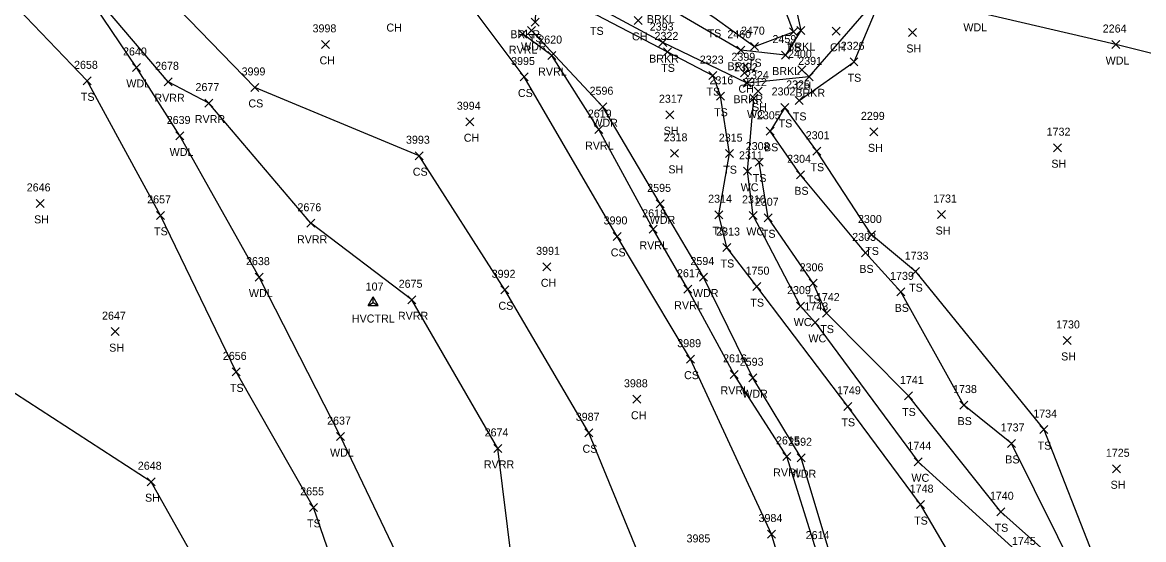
# Model space of a CAD drawing. Extents: x 1482574 to 1485769, y 580696 to 595649.
# Drawn here: x 1484779.3 to 1485059.6, y 582325.6 to 582454.9 of the extents above; entities that cross this region are included whole.
import ezdxf

# ---------------------------------------------------------------- set-up
doc = ezdxf.new("R2010")
doc.units = 0
for name, color, linetype in [('C_A', 7, 'Continuous'), ('C_I', 7, 'Continuous'), ('CPSM', 7, 'Continuous'), ('L_A', 7, 'Continuous'), ('L_I', 7, 'Continuous'), ('L_TIC', 7, 'Continuous'), ('LAWA', 7, 'Continuous'), ('LAWE', 7, 'Continuous'), ('LELB', 7, 'Continuous'), ('LSOGP', 7, 'Continuous')]:
    doc.layers.add(name, color=color, linetype=linetype)

msp = doc.modelspace()

# ---------------------------------------------------------------- linework, layer by layer
at = {"layer": 'CPSM'}
for p, q in [((1484865.7, 582384.13), (1484866.95, 582386.3)), ((1484865.7, 582384.13), (1484866.95, 582384.85)), ((1484865.7, 582384.13), (1484868.2, 582384.13)), ((1484868.2, 582384.13), (1484866.95, 582386.3)), ((1484866.95, 582384.85), (1484866.95, 582386.3)), ((1484866.95, 582384.85), (1484866.95, 582384.85)), ((1484866.95, 582384.85), (1484868.2, 582384.13))]:
    msp.add_line(p, q, dxfattribs=at)
at = {"layer": 'L_TIC'}
for points in [[(1484905.56, 582451.88), (1484907.56, 582453.88)], [(1484907.56, 582451.88), (1484905.56, 582453.88)], [(1484906.45, 582453.96), (1484908.45, 582455.96)], [(1484908.45, 582453.96), (1484906.45, 582455.96)], [(1484932.17, 582454.41), (1484934.17, 582456.41)], [(1484934.17, 582454.41), (1484932.17, 582456.41)], [(1484972.84, 582451.87), (1484974.84, 582453.87)], [(1484974.84, 582451.87), (1484972.84, 582453.87)], [(1484903.31, 582451.08), (1484905.31, 582453.08)], [(1484905.31, 582451.08), (1484903.31, 582453.08)], [(1484971.06, 582451.57), (1484973.06, 582453.57)], [(1484973.06, 582451.57), (1484971.06, 582453.57)], [(1484981.67, 582451.67), (1484983.67, 582453.67)], [(1484983.67, 582451.67), (1484981.67, 582453.67)], [(1485000.76, 582451.38), (1485002.76, 582453.38)], [(1485002.76, 582451.38), (1485000.76, 582453.38)], [(1484854.07, 582448.41), (1484856.07, 582450.41)], [(1484856.07, 582448.41), (1484854.07, 582450.41)], [(1484938.36, 582448.84), (1484940.36, 582450.84)], [(1484940.36, 582448.84), (1484938.36, 582450.84)], [(1484939.56, 582446.53), (1484941.56, 582448.53)], [(1484941.56, 582446.53), (1484939.56, 582448.53)], [(1484957.9, 582446.95), (1484959.9, 582448.95)], [(1484959.9, 582446.95), (1484957.9, 582448.95)], [(1484961.25, 582447.84), (1484963.25, 582449.84)], [(1484963.25, 582447.84), (1484961.25, 582449.84)], [(1485051.65, 582448.37), (1485053.65, 582450.37)], [(1485053.65, 582448.37), (1485051.65, 582450.37)], [(1485051.65, 582448.37), (1485053.65, 582450.37)], [(1485053.65, 582448.37), (1485051.65, 582450.37)], [(1484910.63, 582445.6), (1484912.63, 582447.6)], [(1484912.63, 582445.6), (1484910.63, 582447.6)], [(1484969.06, 582445.73), (1484971.06, 582447.73)], [(1484971.06, 582445.73), (1484969.06, 582447.73)], [(1484986.17, 582444.06), (1484988.16, 582446.06)], [(1484988.16, 582444.06), (1484986.17, 582446.06)], [(1484806.83, 582442.63), (1484808.83, 582444.63)], [(1484808.83, 582442.63), (1484806.83, 582444.63)], [(1484950.88, 582440.6), (1484952.88, 582442.6)], [(1484952.88, 582440.6), (1484950.88, 582442.6)], [(1484958.79, 582441.31), (1484960.79, 582443.31)], [(1484960.79, 582441.31), (1484958.79, 582443.31)], [(1484973.09, 582442.04), (1484975.09, 582444.03)], [(1484975.09, 582442.04), (1484973.09, 582444.03)], [(1484794.49, 582439.29), (1484796.49, 582441.29)], [(1484796.49, 582439.29), (1484794.49, 582441.29)], [(1484814.75, 582439.05), (1484816.75, 582441.05)], [(1484816.75, 582439.05), (1484814.75, 582441.05)], [(1484903.71, 582440.25), (1484905.71, 582442.25)], [(1484905.71, 582440.25), (1484903.71, 582442.25)], [(1484959.42, 582438.71), (1484961.42, 582440.7)], [(1484961.42, 582438.71), (1484959.42, 582440.7)], [(1484974.92, 582440.29), (1484976.92, 582442.29)], [(1484976.92, 582440.29), (1484974.92, 582442.29)], [(1484836.34, 582437.64), (1484838.34, 582439.64)], [(1484838.34, 582437.64), (1484836.34, 582439.64)], [(1484952.78, 582435.43), (1484954.78, 582437.43)], [(1484954.78, 582435.43), (1484952.78, 582437.43)], [(1484961.13, 582434.96), (1484963.12, 582436.96)], [(1484963.12, 582434.96), (1484961.13, 582436.96)], [(1484962.18, 582436.72), (1484964.18, 582438.72)], [(1484964.18, 582436.72), (1484962.18, 582438.72)], [(1484824.86, 582433.73), (1484826.86, 582435.73)], [(1484826.86, 582433.73), (1484824.86, 582435.73)], [(1484923.38, 582432.82), (1484925.38, 582434.81)], [(1484925.38, 582432.82), (1484923.38, 582434.81)], [(1484968.91, 582432.64), (1484970.91, 582434.63)], [(1484970.91, 582432.64), (1484968.91, 582434.63)], [(1484972.46, 582434.39), (1484974.46, 582436.39)], [(1484974.46, 582434.39), (1484972.46, 582436.39)], [(1484940.09, 582430.81), (1484942.09, 582432.81)], [(1484942.09, 582430.81), (1484940.09, 582432.81)], [(1484890.13, 582429.07), (1484892.13, 582431.06)], [(1484892.13, 582429.07), (1484890.13, 582431.06)], [(1484922.38, 582427.1), (1484924.37, 582429.1)], [(1484924.37, 582427.1), (1484922.38, 582429.1)], [(1484965.22, 582426.67), (1484967.22, 582428.67)], [(1484967.22, 582426.67), (1484965.22, 582428.67)], [(1484991.16, 582426.53), (1484993.16, 582428.53)], [(1484993.16, 582426.53), (1484991.16, 582428.53)], [(1484817.67, 582425.5), (1484819.67, 582427.5)], [(1484819.67, 582425.5), (1484817.67, 582427.5)], [(1484941.27, 582421.16), (1484943.27, 582423.16)], [(1484943.27, 582421.16), (1484941.27, 582423.16)], [(1484955.07, 582421.08), (1484957.07, 582423.08)], [(1484957.07, 582421.08), (1484955.07, 582423.08)], [(1484976.87, 582421.69), (1484978.87, 582423.69)], [(1484978.87, 582421.69), (1484976.87, 582423.69)], [(1485037.01, 582422.57), (1485039.01, 582424.57)], [(1485039.01, 582422.57), (1485037.01, 582424.57)], [(1484877.43, 582420.56), (1484879.43, 582422.56)], [(1484879.43, 582420.56), (1484877.43, 582422.56)], [(1484962.44, 582418.97), (1484964.44, 582420.97)], [(1484964.44, 582418.97), (1484962.44, 582420.97)], [(1484959.53, 582416.67), (1484961.53, 582418.67)], [(1484961.53, 582416.67), (1484959.53, 582418.67)], [(1484972.8, 582415.79), (1484974.79, 582417.79)], [(1484974.79, 582415.79), (1484972.8, 582417.79)], [(1484782.72, 582408.64), (1484784.72, 582410.64)], [(1484784.72, 582408.64), (1484782.72, 582410.64)], [(1484937.73, 582408.53), (1484939.73, 582410.53)], [(1484939.73, 582408.53), (1484937.73, 582410.53)], [(1484812.78, 582405.65), (1484814.78, 582407.65)], [(1484814.78, 582405.65), (1484812.78, 582407.65)], [(1484952.4, 582405.81), (1484954.4, 582407.81)], [(1484954.4, 582405.81), (1484952.4, 582407.81)], [(1484960.95, 582405.63), (1484962.95, 582407.63)], [(1484962.95, 582405.63), (1484960.95, 582407.63)], [(1484964.72, 582405.04), (1484966.72, 582407.04)], [(1484966.72, 582405.04), (1484964.72, 582407.04)], [(1485008.07, 582405.86), (1485010.07, 582407.86)], [(1485010.07, 582405.86), (1485008.07, 582407.86)], [(1484850.4, 582403.67), (1484852.4, 582405.67)], [(1484852.4, 582403.67), (1484850.4, 582405.67)], [(1484935.96, 582402.16), (1484937.96, 582404.16)], [(1484937.96, 582402.16), (1484935.96, 582404.16)], [(1484926.92, 582400.38), (1484928.92, 582402.38)], [(1484928.92, 582400.38), (1484926.92, 582402.38)], [(1484990.57, 582400.75), (1484992.57, 582402.75)], [(1484992.57, 582400.75), (1484990.57, 582402.75)], [(1484954.4, 582397.62), (1484956.4, 582399.61)], [(1484956.4, 582397.62), (1484954.4, 582399.61)], [(1484989.06, 582396.26), (1484991.06, 582398.26)], [(1484991.06, 582396.26), (1484989.06, 582398.26)], [(1484837.48, 582390.2), (1484839.48, 582392.2)], [(1484839.48, 582390.2), (1484837.48, 582392.2)], [(1484909.39, 582392.78), (1484911.39, 582394.78)], [(1484911.39, 582392.78), (1484909.39, 582394.78)], [(1484948.53, 582390.22), (1484950.53, 582392.22)], [(1484950.53, 582390.22), (1484948.53, 582392.22)], [(1485001.53, 582391.58), (1485003.53, 582393.57)], [(1485003.53, 582391.58), (1485001.53, 582393.57)], [(1484961.85, 582387.82), (1484963.85, 582389.82)], [(1484963.85, 582387.82), (1484961.85, 582389.82)], [(1484975.96, 582388.66), (1484977.96, 582390.66)], [(1484977.96, 582388.66), (1484975.96, 582390.66)], [(1484875.65, 582384.54), (1484877.65, 582386.54)], [(1484877.65, 582384.54), (1484875.65, 582386.54)], [(1484898.85, 582387.04), (1484900.85, 582389.04)], [(1484900.85, 582387.04), (1484898.85, 582389.04)], [(1484944.65, 582387.18), (1484946.65, 582389.18)], [(1484946.65, 582387.18), (1484944.65, 582389.18)], [(1484997.89, 582386.52), (1484999.89, 582388.52)], [(1484999.89, 582386.52), (1484997.89, 582388.52)], [(1484972.78, 582382.96), (1484974.78, 582384.96)], [(1484974.78, 582382.96), (1484972.78, 582384.96)], [(1484976.46, 582378.89), (1484978.46, 582380.88)], [(1484978.46, 582378.89), (1484976.46, 582380.88)], [(1484979.33, 582381.21), (1484981.33, 582383.21)], [(1484981.33, 582381.21), (1484979.33, 582383.21)], [(1484801.48, 582376.57), (1484803.48, 582378.57)], [(1484803.48, 582376.57), (1484801.48, 582378.57)], [(1485039.46, 582374.37), (1485041.46, 582376.37)], [(1485041.46, 582374.37), (1485039.46, 582376.37)], [(1484945.25, 582369.7), (1484947.25, 582371.69)], [(1484947.25, 582369.7), (1484945.25, 582371.69)], [(1484831.75, 582366.51), (1484833.75, 582368.51)], [(1484833.75, 582366.51), (1484831.75, 582368.51)], [(1484956.22, 582365.89), (1484958.22, 582367.89)], [(1484958.22, 582365.89), (1484956.22, 582367.89)], [(1484960.86, 582365.04), (1484962.86, 582367.04)], [(1484962.86, 582365.04), (1484960.86, 582367.04)], [(1484931.91, 582359.66), (1484933.91, 582361.66)], [(1484933.91, 582359.66), (1484931.91, 582361.66)], [(1484999.78, 582360.48), (1485001.78, 582362.48)], [(1485001.78, 582360.48), (1484999.78, 582362.48)], [(1484984.61, 582357.89), (1484986.61, 582359.89)], [(1484986.61, 582357.89), (1484984.61, 582359.89)], [(1485013.62, 582358.21), (1485015.62, 582360.21)], [(1485015.62, 582358.21), (1485013.62, 582360.21)], [(1484919.86, 582351.28), (1484921.86, 582353.28)], [(1484921.86, 582351.28), (1484919.86, 582353.28)], [(1485033.66, 582352.07), (1485035.66, 582354.07)], [(1485035.66, 582352.07), (1485033.66, 582354.07)], [(1484857.76, 582350.32), (1484859.76, 582352.32)], [(1484859.76, 582350.32), (1484857.76, 582352.32)], [(1485025.53, 582348.61), (1485027.53, 582350.61)], [(1485027.53, 582348.61), (1485025.53, 582350.61)], [(1484897.14, 582347.38), (1484899.14, 582349.38)], [(1484899.14, 582347.38), (1484897.14, 582349.38)], [(1484969.4, 582345.35), (1484971.4, 582347.35)], [(1484971.4, 582345.35), (1484969.4, 582347.35)], [(1484972.98, 582345.03), (1484974.98, 582347.03)], [(1484974.98, 582345.03), (1484972.98, 582347.03)], [(1485002.21, 582344.02), (1485004.21, 582346.02)], [(1485004.21, 582344.02), (1485002.21, 582346.02)], [(1485051.81, 582342.28), (1485053.81, 582344.28)], [(1485053.81, 582342.28), (1485051.81, 582344.28)], [(1484810.44, 582339.04), (1484812.44, 582341.04)], [(1484812.44, 582339.04), (1484810.44, 582341.04)], [(1484851.03, 582332.63), (1484853.03, 582334.63)], [(1484853.03, 582332.63), (1484851.03, 582334.63)], [(1485002.78, 582333.32), (1485004.78, 582335.32)], [(1485004.78, 582333.32), (1485002.78, 582335.32)], [(1485022.91, 582331.53), (1485024.91, 582333.53)], [(1485024.91, 582331.53), (1485022.91, 582333.53)], [(1484965.56, 582325.96), (1484967.56, 582327.96)], [(1484967.56, 582325.96), (1484965.56, 582327.96)]]:
    msp.add_lwpolyline(points, dxfattribs=at)
at = {"layer": 'LAWA'}
for points in [[(1485052.65, 582449.37), (1485017.08, 582457.66), (1485002.64, 582478.08), (1485021.27, 582509.11), (1485017.76, 582533.46)], [(1484807.83, 582443.63), (1484789.25, 582471.18)], [(1485023.81, 582236.06), (1485015.12, 582258.42), (1485005.47, 582274.43), (1484995.42, 582298.07), (1484981.65, 582320.46), (1484973.98, 582346.03), (1484961.86, 582366.04), (1484949.53, 582391.22), (1484938.73, 582409.53), (1484924.38, 582433.81), (1484906.56, 582452.88)], [(1485075.38, 582443.68), (1485052.65, 582449.37)], [(1484915.16, 582216.76), (1484906.84, 582246.58), (1484892.49, 582281.5), (1484876.39, 582314.59), (1484858.76, 582351.32), (1484838.48, 582391.2), (1484818.67, 582426.5), (1484807.83, 582443.63)]]:
    msp.add_lwpolyline(points, dxfattribs=at)
at = {"layer": 'LAWE'}
for points in [[(1484901.73, 582319.41), (1484898.14, 582348.38), (1484876.65, 582385.54), (1484851.4, 582404.67), (1484825.86, 582434.73), (1484815.75, 582440.05), (1484789.25, 582471.18), (1484766.91, 582495.26), (1484752.64, 582511.53), (1484735.04, 582527.7), (1484703.7, 582557.49), (1484683.77, 582582.65), (1484658.88, 582608.94), (1484640.93, 582626.78), (1484617.5, 582643.87), (1484591.41, 582664.84), (1484560.44, 582694.18), (1484551.66, 582704.27)], [(1484971.03, 582465.85), (1484973.84, 582452.87), (1484970.06, 582446.73), (1484958.9, 582447.95), (1484938.74, 582459.73)], [(1484992.4, 582460.31), (1484975.91, 582441.29), (1484960.42, 582439.7), (1484939.36, 582449.84), (1484914.7, 582463.21)], [(1485020.35, 582235.16), (1485012.7, 582253.51), (1485004.73, 582270.58), (1484994.55, 582289.28), (1484987.31, 582307.44), (1484977.82, 582322.68), (1484970.4, 582346.35), (1484957.22, 582366.89), (1484945.65, 582388.18), (1484936.96, 582403.16), (1484923.38, 582428.1), (1484911.63, 582446.6), (1484904.31, 582452.08)], [(1484973.78, 582383.96), (1484961.95, 582406.63), (1484960.53, 582417.67), (1484962.12, 582435.96)], [(1484977.46, 582379.88), (1484973.78, 582383.96)], [(1484977.46, 582379.88), (1485003.21, 582345.02), (1485029.34, 582321.23), (1485042.39, 582302.12)]]:
    msp.add_lwpolyline(points, dxfattribs=at)
at = {"layer": 'LELB'}
for points in [[(1484934.85, 582318.2), (1484920.86, 582352.28), (1484899.85, 582388.04), (1484878.43, 582421.56), (1484837.34, 582438.64), (1484810.09, 582466.84), (1484787.01, 582495.34), (1484738.45, 582543.61), (1484700.5, 582575.43), (1484669.74, 582613.45), (1484643.11, 582644.14), (1484614.76, 582674.75), (1484580.8, 582689.68), (1484560.67, 582749.78), (1484522.57, 582766.54), (1484495.71, 582790.58), (1484464.85, 582810.97), (1484442.2, 582833.83)], [(1485002.93, 582233.34), (1484992.5, 582263.93), (1484974.17, 582301.29), (1484966.56, 582326.96), (1484946.25, 582370.69), (1484927.92, 582401.38), (1484904.71, 582441.25), (1484886.96, 582465.01), (1484858.7, 582503.29), (1484852.02, 582537.03), (1484804.34, 582588.15), (1484752.2, 582627.41), (1484731.88, 582664.77), (1484681.4, 582685.05), (1484649.84, 582708.59), (1484625.24, 582730.73), (1484593.85, 582761.39), (1484564.6, 582801.05), (1484536.81, 582827.49)], [(1484893.16, 582225.95), (1484874.47, 582260.96), (1484864.03, 582298.79), (1484852.03, 582333.63), (1484832.75, 582367.51), (1484813.78, 582406.65), (1484795.49, 582440.29), (1484770.46, 582466.4), (1484758.58, 582490.95), (1484746.62, 582505.31), (1484737.12, 582520.69), (1484722.27, 582524.68), (1484701.74, 582544.16), (1484684.49, 582562.93), (1484659.56, 582590.31)], [(1484891.21, 582479.17), (1484911.84, 582482.73), (1484927.48, 582474.11), (1484942.04, 582462.79), (1484952.15, 582456.18), (1484962.25, 582448.84), (1484972.06, 582452.57), (1484968.93, 582460.74), (1484958, 582466.03), (1484943.4, 582468.53), (1484932.43, 582474.41), (1484926.65, 582494.11), (1484925.84, 582513.13), (1484942.72, 582524.44)], [(1484907.45, 582454.96), (1484907.96, 582460.72), (1484922.76, 582456.78), (1484940.56, 582447.53), (1484951.88, 582441.6)], [(1484973.46, 582435.39), (1484987.17, 582445.06), (1484994.03, 582461.4)], [(1484951.88, 582441.6), (1484953.78, 582436.43)], [(1484955.4, 582398.61), (1484953.4, 582406.81), (1484956.07, 582422.08), (1484953.78, 582436.43)], [(1484969.91, 582433.64), (1484966.22, 582427.67)], [(1484991.57, 582401.75), (1484977.87, 582422.69), (1484969.91, 582433.64)], [(1484990.06, 582397.26), (1484973.79, 582416.79), (1484966.22, 582427.67)], [(1484976.96, 582389.66), (1484965.72, 582406.04), (1484963.44, 582419.97)], [(1485002.53, 582392.57), (1484991.57, 582401.75)], [(1484962.85, 582388.82), (1484955.4, 582398.61)], [(1484998.89, 582387.52), (1484990.06, 582397.26)], [(1485002.53, 582392.57), (1485034.66, 582353.07), (1485047.57, 582320.05)], [(1484980.33, 582382.21), (1484976.96, 582389.66)], [(1485017.15, 582311.55), (1485003.78, 582334.32), (1484985.61, 582358.89), (1484962.85, 582388.82)], [(1485043.9, 582314.68), (1485026.53, 582349.61), (1485014.62, 582359.21), (1484998.89, 582387.52)], [(1485043.9, 582314.68), (1485023.91, 582332.53), (1485000.78, 582361.48), (1484980.33, 582382.21)]]:
    msp.add_lwpolyline(points, dxfattribs=at)
at = {"layer": 'LSOGP'}
msp.add_lwpolyline([(1484830.67, 582305.91), (1484811.44, 582340.04), (1484768.18, 582368.05), (1484699.19, 582421.32), (1484668.76, 582398.66), (1484667.38, 582397.93), (1484663.13, 582397.27), (1484659.52, 582402.29), (1484645.53, 582403.2), (1484623.23, 582396.94), (1484591.95, 582378.91), (1484565.74, 582372.21), (1484555.58, 582371.9), (1484536.19, 582371.12), (1484521.6, 582394.68), (1484517.63, 582409.84), (1484514.18, 582420.74), (1484512.29, 582440.31), (1484507.38, 582468.85), (1484496.79, 582480.07), (1484475.26, 582497.56), (1484469.2, 582496.81), (1484449.6, 582507.61), (1484397.45, 582542.25)], dxfattribs=at)

# ---------------------------------------------------------------- texts
at = {"layer": 'C_A'}
msp.add_text('HVCTRL', height=2, dxfattribs=at).set_placement((1484861.64, 582379.85))
at = {"layer": 'C_I'}
msp.add_text('107', height=2, dxfattribs=at).set_placement((1484865.08, 582387.85))
at = {"layer": 'L_A'}
for s, p in [('BRKL', (1484935.38, 582454.73)), ('CH', (1484870.28, 582452.61)), ('TS', (1484921.17, 582451.78)), ('WDL', (1485014.5, 582452.66)), ('BRKR', (1484901.25, 582450.93)), ('TS', (1484905.86, 582449.96)), ('CH', (1484931.66, 582450.41)), ('TS', (1484950.56, 582451.18)), ('RVRL', (1484900.88, 582447.08)), ('WDR', (1484903.93, 582447.88)), ('TS', (1484970.47, 582447.57)), ('BRKL', (1484970.49, 582447.87)), ('CH', (1484981.16, 582447.67)), ('SH', (1485000.25, 582447.38)), ('CH', (1484853.56, 582444.41)), ('BRKR', (1484935.95, 582444.84)), ('TS', (1484960.66, 582443.84)), ('WDL', (1485050.07, 582444.37)), ('WDL', (1485050.07, 582444.37)), ('RVRL', (1484908.2, 582441.6)), ('TS', (1484938.97, 582442.53)), ('BRKL', (1484955.54, 582442.95)), ('BRKL', (1484966.71, 582441.73)), ('WDL', (1484805.25, 582438.63)), ('CH', (1484972.58, 582438.04)), ('TS', (1484985.57, 582440.06)), ('TS', (1484793.89, 582435.29)), ('RVRR', (1484812.27, 582435.05)), ('CS', (1484903.15, 582436.25)), ('TS', (1484950.29, 582436.6)), ('CH', (1484958.28, 582437.31)), ('BRKR', (1484972.51, 582436.29)), ('CS', (1484835.78, 582433.64)), ('BRKR', (1484957.01, 582434.7)), ('SH', (1484961.67, 582432.72)), ('RVRR', (1484822.37, 582429.73)), ('TS', (1484952.19, 582431.43)), ('WC', (1484960.43, 582430.96)), ('TS', (1484971.87, 582430.39)), ('WDR', (1484921.74, 582428.81)), ('SH', (1484939.58, 582426.81)), ('TS', (1484968.32, 582428.64)), ('CH', (1484889.62, 582425.06)), ('WDL', (1484816.08, 582421.5)), ('RVRL', (1484919.94, 582423.1)), ('BS', (1484964.66, 582422.67)), ('SH', (1484990.65, 582422.53)), ('SH', (1485036.5, 582418.57)), ('CS', (1484876.87, 582416.56)), ('SH', (1484940.76, 582417.16)), ('TS', (1484954.48, 582417.08)), ('TS', (1484976.28, 582417.69)), ('WC', (1484958.84, 582412.67)), ('TS', (1484961.85, 582414.97)), ('BS', (1484972.24, 582411.79)), ('SH', (1484782.21, 582404.64)), ('WDR', (1484936.1, 582404.53)), ('TS', (1484812.19, 582401.65)), ('TS', (1484951.8, 582401.81)), ('WC', (1484960.26, 582401.63)), ('SH', (1485007.56, 582401.86)), ('RVRR', (1484847.92, 582399.67)), ('TS', (1484964.13, 582401.04)), ('CS', (1484926.36, 582396.38)), ('RVRL', (1484933.52, 582398.16)), ('TS', (1484989.98, 582396.75)), ('TS', (1484953.81, 582393.61)), ('BS', (1484988.5, 582392.26)), ('CH', (1484908.88, 582388.78)), ('TS', (1485000.94, 582387.57)), ('WDL', (1484835.89, 582386.2)), ('WDR', (1484946.89, 582386.22)), ('TS', (1484975.37, 582384.66)), ('CS', (1484898.29, 582383.04)), ('RVRL', (1484942.22, 582383.18)), ('TS', (1484961.26, 582383.82)), ('BS', (1484997.33, 582382.52)), ('RVRR', (1484873.16, 582380.54)), ('WC', (1484972.09, 582378.96)), ('TS', (1484978.74, 582377.21)), ('WC', (1484975.77, 582374.89)), ('SH', (1484800.97, 582372.57)), ('SH', (1485038.95, 582370.37)), ('CS', (1484944.69, 582365.69)), ('TS', (1484831.16, 582362.51)), ('RVRL', (1484953.79, 582361.89)), ('WDR', (1484959.22, 582361.04)), ('TS', (1484999.19, 582356.48)), ('CH', (1484931.4, 582355.66)), ('TS', (1484984.02, 582353.89)), ('BS', (1485013.06, 582354.21)), ('TS', (1485033.07, 582348.07)), ('WDL', (1484856.18, 582346.32)), ('CS', (1484919.3, 582347.28)), ('RVRR', (1484894.65, 582343.38)), ('BS', (1485024.97, 582344.61)), ('RVRL', (1484966.96, 582341.35)), ('WDR', (1484971.34, 582341.03)), ('WC', (1485001.52, 582340.02)), ('SH', (1485051.3, 582338.28)), ('SH', (1484809.93, 582335.04)), ('TS', (1484850.44, 582328.63)), ('TS', (1485002.19, 582329.32)), ('TS', (1485022.32, 582327.53))]:
    msp.add_text(s, height=2, dxfattribs=at).set_placement(p)
at = {"layer": 'L_I'}
for s, p in [('3998', (1484851.81, 582452.41)), ('2393', (1484936.1, 582452.84)), ('2470', (1484958.9, 582451.84)), ('2264', (1485049.34, 582452.37)), ('2264', (1485049.34, 582452.37)), ('2620', (1484908.24, 582449.6)), ('2322', (1484937.3, 582450.53)), ('2460', (1484955.5, 582450.95)), ('2459', (1484966.79, 582449.73)), ('2640', (1484804.43, 582446.63)), ('2326', (1484983.85, 582448.06)), ('2658', (1484792.18, 582443.29)), ('3995', (1484901.45, 582444.25)), ('2323', (1484948.62, 582444.6)), ('2399', (1484956.52, 582445.31)), ('2400', (1484970.66, 582446.04)), ('2391', (1484973.22, 582444.29)), ('2678', (1484812.45, 582443.05)), ('3999', (1484834.07, 582441.64)), ('2392', (1484957.16, 582442.7)), ('2324', (1484959.92, 582440.72)), ('2677', (1484822.55, 582437.73)), ('2316', (1484951.03, 582439.43)), ('2312', (1484959.43, 582438.96)), ('2325', (1484970.2, 582438.39)), ('2596', (1484921.06, 582436.81)), ('2302', (1484966.57, 582436.64)), ('3994', (1484887.87, 582433.06)), ('2317', (1484938.4, 582434.81)), ('2639', (1484815.35, 582429.5)), ('2619', (1484920.63, 582431.1)), ('2305', (1484962.88, 582430.67)), ('2299', (1484988.89, 582430.53)), ('1732', (1485035.32, 582426.57)), ('3993', (1484875.17, 582424.56)), ('2318', (1484939.58, 582425.16)), ('2315', (1484953.37, 582425.08)), ('2301', (1484975.1, 582425.69)), ('2308', (1484960.1, 582422.97)), ('2311', (1484958.41, 582420.67)), ('2304', (1484970.46, 582419.79)), ('2646', (1484780.36, 582412.64)), ('2595', (1484935.47, 582412.53)), ('2657', (1484810.47, 582409.65)), ('2314', (1484950.7, 582409.81)), ('2310', (1484959.17, 582409.63)), ('1731', (1485006.95, 582409.86)), ('2676', (1484848.04, 582407.67)), ('2307', (1484962.38, 582409.04)), ('3990', (1484924.57, 582404.38)), ('2618', (1484934.22, 582406.16)), ('2300', (1484988.15, 582404.75)), ('2313', (1484952.71, 582401.61)), ('2303', (1484986.72, 582400.26)), ('3991', (1484907.7, 582396.78)), ('2638', (1484835.17, 582394.2)), ('2594', (1484946.27, 582394.22)), ('1733', (1484999.84, 582395.57)), ('3992', (1484896.59, 582391.04)), ('2617', (1484942.91, 582391.18)), ('1750', (1484960.07, 582391.82)), ('2306', (1484973.57, 582392.66)), ('1739', (1484996.19, 582390.52)), ('2675', (1484873.34, 582388.54)), ('2309', (1484970.43, 582386.96)), ('1742', (1484977.64, 582385.21)), ('1743', (1484974.77, 582382.89)), ('2647', (1484799.18, 582380.57)), ('1730', (1485037.68, 582378.37)), ('3989', (1484942.98, 582373.69)), ('2656', (1484829.38, 582370.51)), ('2616', (1484954.43, 582369.89)), ('2593', (1484958.6, 582369.04)), ('3988', (1484929.65, 582363.66)), ('1741', (1484998.65, 582364.48)), ('1738', (1485011.93, 582362.21)), ('1749', (1484982.91, 582361.89)), ('2637', (1484855.45, 582354.32)), ('3987', (1484917.6, 582355.28)), ('1734', (1485031.97, 582356.07)), ('2674', (1484894.83, 582351.38)), ('1737', (1485023.84, 582352.61)), ('2615', (1484967.66, 582349.35)), ('2592', (1484970.72, 582349.03)), ('1744', (1485000.52, 582348.02)), ('1725', (1485050.12, 582346.28)), ('2648', (1484808.13, 582343.04)), ('1748', (1485001.09, 582337.32)), ('2655', (1484848.72, 582336.63)), ('1740', (1485021.13, 582335.53)), ('3984', (1484963.3, 582329.96)), ('2614', (1484975.08, 582325.68)), ('3985', (1484945.3, 582324.86)), ('1745', (1485026.65, 582324.23))]:
    msp.add_text(s, height=2, dxfattribs=at).set_placement(p)

doc.saveas('drawing.dxf')
